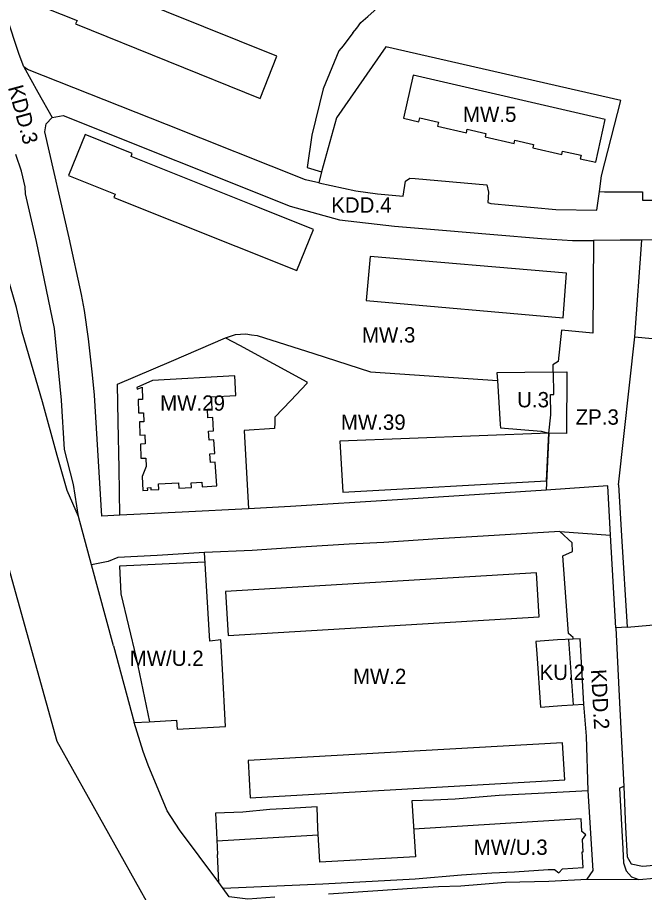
# Model space of a CAD drawing. Extents: x 7426178 to 7427732, y 5548847 to 5550287.
# Drawn here: x 7427012.7 to 7427197, y 5549022.7 to 5549279.8 of the extents above; entities that cross this region are included whole.
import ezdxf

# ---------------------------------------------------------------- set-up
doc = ezdxf.new("R2010")
doc.units = 0
for name, color, linetype in [('linie_rozgraniczajace', 7, 'Continuous'), ('linie_zabudowy_nieprzekraczalne', 7, 'Continuous'), ('linie_zabudowy_obowiazujace', 7, 'Continuous'), ('oznaczenia_przeznaczen', 7, 'Continuous')]:
    doc.layers.add(name, color=color, linetype=linetype)

msp = doc.modelspace()

# ---------------------------------------------------------------- linework, layer by layer
at = {"layer": 'linie_rozgraniczajace'}
for p, q in [((7427013.82, 5549234.68), (7427012.24, 5549239.56)), ((7427018.29, 5549214.04), (7427015, 5549228.01)), ((7427023.56, 5549188.43), (7427018.29, 5549214.04)), ((7427194.13, 5549185.96), (7427196.16, 5549214.45)), ((7427025.64, 5549167.34), (7427023.56, 5549188.43)), ((7427030.65, 5549133.22), (7427027.29, 5549140.82)), ((7427168.06, 5549140.91), (7427168.06, 5549140.91)), ((7427172.12, 5549128.78), (7427187, 5549127.76)), ((7427188.56, 5549100.49), (7427188.56, 5549100.49)), ((7427180.09, 5549026.66), (7427195.3, 5549026.51))]:
    msp.add_line(p, q, dxfattribs=at)
for points in [[(7426806.41, 5549611.72), (7426845.02, 5549569.73), (7426883.5, 5549515.53), (7426907.93, 5549461.17), (7426932.17, 5549384.03), (7426948.93, 5549331.51), (7426962.26, 5549289.73), (7427024.27, 5549067.18), (7427061.13, 5549001.37), (7427073.43, 5548973.27), (7427176.69, 5548896.63), (7427213.08, 5548849.03)], [(7427111.3, 5549275.29), (7427112.42, 5549276.71), (7427113.63, 5549278.4), (7427115.63, 5549280.17), (7427121.01, 5549284.98), (7427123.37, 5549287.21), (7427128.8, 5549292.12), (7427130.82, 5549293.83), (7427131.43, 5549294.45), (7427134.33, 5549296.6), (7427143.02, 5549303.88), (7427149.6, 5549309.36), (7427153.81, 5549312.46), (7427154.8, 5549315.39), (7427150.02, 5549327.69), (7427166.15, 5549333.81), (7427181.85, 5549339.96), (7427249.51, 5549363.69), (7427309.23, 5549379.16)], [(7427013.13, 5549268.92), (7427005.61, 5549291.59), (7427005.47, 5549294.05), (7427002.49, 5549302.88), (7427002.29, 5549306.24), (7427003.23, 5549308.53), (7427005.69, 5549310.69), (7427031.81, 5549323.48), (7427048.39, 5549331.54), (7427056.79, 5549335.77), (7427084.49, 5549349.29), (7427088.69, 5549351.18), (7427088.82, 5549351.24)], [(7427027.29, 5549140.82), (7427024.38, 5549151.16), (7427019.99, 5549166.88), (7427014.09, 5549187.33), (7427012.41, 5549194.63), (7427003.06, 5549226.37), (7426993.93, 5549257.37), (7426990.69, 5549268.36), (7426989.92, 5549277.44), (7426988.58, 5549283.13), (7426984.1, 5549295.88), (7426984.96, 5549299.25), (7426984.16, 5549301.77), (7426989.3, 5549304.41)], [(7427111.3, 5549275.29), (7427108.46, 5549271.56), (7427107.18, 5549270.01), (7427105.09, 5549265.06), (7427102.55, 5549258.9), (7427099.22, 5549245.24), (7427097.84, 5549235.74)], [(7427121, 5549271.19), (7427106.5, 5549250.33), (7427102.07, 5549234.44)], [(7427183.74, 5549228.7), (7427184.38, 5549233.33), (7427190.02, 5549255.46), (7427121, 5549271.19)], [(7427101.22, 5549231.21), (7427097.34, 5549232.16), (7427056.49, 5549248.38), (7427015.64, 5549264.59), (7427014.53, 5549265.37), (7427013.13, 5549268.92)], [(7427014.53, 5549265.37), (7427018.68, 5549257.92), (7427022.83, 5549250.47)], [(7427037.44, 5549133.27), (7427035.3, 5549168.88), (7427034.73, 5549174.79), (7427033.57, 5549185.38), (7427032.35, 5549193.71), (7427031.53, 5549198.39), (7427027.87, 5549215.06), (7427020.77, 5549246.25), (7427021.15, 5549248.57), (7427022.83, 5549250.47)], [(7427022.83, 5549250.47), (7427026.11, 5549251.01), (7427092.81, 5549224.37), (7427107.38, 5549220.37), (7427123.55, 5549218.53), (7427137.62, 5549217.31), (7427152.66, 5549216.04), (7427166.74, 5549214.87), (7427175.83, 5549214.34), (7427182.03, 5549214.34), (7427181.83, 5549187.11), (7427172.56, 5549187.95), (7427171.57, 5549178.74), (7427170.07, 5549177.78), (7427170.02, 5549175.66), (7427153.62, 5549175.37), (7427153.76, 5549173.17), (7427154.61, 5549160.21)], [(7427015, 5549228.01), (7427014.91, 5549230.12), (7427013.82, 5549234.68)], [(7427097.84, 5549235.74), (7427102.07, 5549234.44), (7427101.22, 5549231.21), (7427112.11, 5549228.91), (7427118.54, 5549228.02), (7427126.1, 5549227.31), (7427126.69, 5549231.73), (7427127.97, 5549232.67), (7427129.57, 5549232.55), (7427150.69, 5549230.7), (7427151.17, 5549228.54), (7427150.97, 5549225.49), (7427151.86, 5549225.22), (7427170.89, 5549223.46), (7427182.99, 5549223.23), (7427183.74, 5549228.7), (7427185.28, 5549228.61), (7427196.37, 5549228.64), (7427196.45, 5549226.18), (7427201.6, 5549226.15)], [(7427209.05, 5549214.51), (7427195.81, 5549214.45), (7427189.85, 5549214.39), (7427182.03, 5549214.34)], [(7427042.79, 5549133.55), (7427042.55, 5549147.3), (7427042.31, 5549161.05), (7427042.12, 5549172.05), (7427057.98, 5549178.88), (7427073.84, 5549185.71), (7427077.95, 5549183.5), (7427087.83, 5549178.16), (7427097.71, 5549172.82), (7427097.74, 5549172.25), (7427093.04, 5549167.33), (7427088.33, 5549162.42), (7427088.29, 5549160.74), (7427088.24, 5549159.06)], [(7427073.84, 5549185.71), (7427075.3, 5549186.17), (7427076.76, 5549186.64), (7427078.27, 5549186.74), (7427079.77, 5549186.83), (7427081.44, 5549186.6), (7427083.1, 5549186.37), (7427099.79, 5549181.05), (7427116.49, 5549175.74), (7427153.76, 5549173.17)], [(7427189.39, 5549142.47), (7427194.13, 5549185.96), (7427244.55, 5549181.19), (7427343.09, 5549165.77)], [(7427170.02, 5549175.66), (7427174.13, 5549175.74), (7427174.1, 5549157.56), (7427168.88, 5549157.71), (7427168.06, 5549140.91)], [(7427034.48, 5549118.98), (7427030.65, 5549133.22), (7427029.11, 5549142.56), (7427026.54, 5549152.89), (7427025.64, 5549167.34)], [(7427088.24, 5549159.06), (7427079.34, 5549158.48), (7427080.61, 5549135.5)], [(7427154.61, 5549160.21), (7427154.67, 5549159.23), (7427160.62, 5549158.75), (7427166.57, 5549158.28), (7427168.88, 5549157.71)], [(7427168.06, 5549140.91), (7427124.37, 5549138.13), (7427092.9, 5549136.14), (7427080.61, 5549135.5)], [(7427188.56, 5549100.49), (7427187, 5549127.76), (7427186.18, 5549142.24), (7427168.06, 5549140.91)], [(7427189.39, 5549142.47), (7427190.22, 5549127.54), (7427191.89, 5549100.66), (7427210.8, 5549102.38), (7427213.95, 5549102.67), (7427215.83, 5549102.92)], [(7427080.61, 5549135.5), (7427061.06, 5549134.49), (7427042.79, 5549133.55), (7427037.44, 5549133.27)], [(7427104.06, 5549022.31), (7427130.16, 5549024.09), (7427136.44, 5549024.43), (7427143.04, 5549024.69), (7427156.13, 5549025.7), (7427168.85, 5549026.02), (7427180.09, 5549026.66), (7427181.86, 5549029.14), (7427180.47, 5549052.55), (7427179.96, 5549068.69), (7427179.11, 5549078.01), (7427178.04, 5549097.27), (7427176, 5549097.13), (7427175.98, 5549097.64), (7427174.65, 5549098.78), (7427173.01, 5549121.65), (7427175.87, 5549122.87), (7427175.72, 5549125.48), (7427172.12, 5549128.78), (7427149.57, 5549127.43), (7427136.25, 5549126.63), (7427120.41, 5549125.52), (7427110.16, 5549125.1), (7427095.96, 5549124.17), (7427081.63, 5549123.25), (7427067.61, 5549122.65), (7427053.7, 5549121.78), (7427042.15, 5549121.14), (7427039.31, 5549120.02), (7427034.48, 5549118.98)], [(7427040.87, 5549095.2), (7427046.96, 5549072.63), (7427051.35, 5549072.88), (7427059.44, 5549073.34), (7427059.58, 5549070.73), (7427073.85, 5549071.46), (7427072.97, 5549088.29), (7427072.5, 5549096.98), (7427069.2, 5549096.56), (7427067.61, 5549122.65)], [(7427040.87, 5549095.2), (7427034.48, 5549118.98)], [(7427191.89, 5549100.66), (7427188.56, 5549100.49), (7427189.59, 5549080.43), (7427190.95, 5549053.83), (7427189.64, 5549053.39), (7427190.62, 5549035.51), (7427190.82, 5549031.45), (7427191.61, 5549029.08), (7427193.18, 5549027.34), (7427195.3, 5549026.51), (7427204.57, 5549027.34), (7427204.74, 5549027.89), (7427217.64, 5549028.9), (7427230.78, 5549029.62), (7427244.12, 5549030.67)], [(7427176, 5549097.13), (7427171.41, 5549096.93), (7427165.09, 5549096.51), (7427165.31, 5549092.8), (7427166.42, 5549077.16), (7427172.69, 5549077.63), (7427179.11, 5549078.01)], [(7427088.36, 5549021.31), (7427080.37, 5549020.78), (7427074.88, 5549021.46), (7427071.9, 5549025.67), (7427060.27, 5549041.15), (7427056.72, 5549046.74), (7427051.09, 5549060.09), (7427049.64, 5549064.12), (7427046.96, 5549072.63)], [(7427180.47, 5549052.55), (7427167.58, 5549051.89), (7427154.23, 5549051.2), (7427141.38, 5549050.18), (7427134.93, 5549049.84), (7427128.64, 5549049.66)], [(7427128.64, 5549049.66), (7427129.64, 5549033.23), (7427101.59, 5549031.65), (7427100.99, 5549041.51), (7427100.81, 5549047.84), (7427092.56, 5549047.43), (7427086.89, 5549047.09), (7427078.95, 5549046.33), (7427070.87, 5549046.05), (7427071.17, 5549040.31), (7427071.49, 5549033.9)], [(7427071.9, 5549025.67), (7427071.49, 5549033.9)]]:
    msp.add_lwpolyline(points, dxfattribs=at)
at = {"layer": 'linie_zabudowy_nieprzekraczalne'}
msp.add_line((7427176.08, 5549077.83), (7427174.77, 5549097.08), dxfattribs=at)
for points in [[(7427168.88, 5549157.71), (7427169.46, 5549163.09), (7427169.35, 5549169.04), (7427170.38, 5549169.05), (7427170.26, 5549175.67)], [(7427067.79, 5549119.74), (7427042.67, 5549118.59), (7427043.04, 5549110.48), (7427047.53, 5549091.64), (7427051.52, 5549072.89)], [(7427188.56, 5549100.49), (7427189.59, 5549080.43), (7427190.95, 5549053.83), (7427191.36, 5549041.76), (7427191.91, 5549033.22), (7427193.09, 5549031.1)], [(7427178.37, 5549044.36), (7427129.15, 5549041.33)], [(7427101.1, 5549039.6), (7427071.3, 5549037.76)]]:
    msp.add_lwpolyline(points, dxfattribs=at)
msp.add_lwpolyline([(7427168.88, 5549157.71), (7427107.45, 5549155.3), (7427108.29, 5549140.35), (7427168.2, 5549143.7)], close=True, dxfattribs=at)
at = {"layer": 'linie_zabudowy_obowiazujace'}
for points in [[(7427088.96, 5549268.43), (7427035.01, 5549290.19), (7427035.3, 5549290.91), (7427021.52, 5549296.47), (7427016.64, 5549284.38), (7427030.18, 5549278.92), (7427029.78, 5549277.94), (7427083.97, 5549256.08), (7427088.96, 5549268.43)], [(7427185.47, 5549249.83), (7427128.95, 5549262.91), (7427126.18, 5549250.21), (7427130.66, 5549249.18), (7427130.92, 5549250.32), (7427136.45, 5549249.05), (7427136.19, 5549247.92), (7427144.67, 5549245.98), (7427144.9, 5549246.99), (7427150.37, 5549245.73), (7427150.14, 5549244.73), (7427158.66, 5549242.78), (7427158.89, 5549243.79), (7427164.36, 5549242.53), (7427164.13, 5549241.53), (7427172.66, 5549239.58), (7427172.89, 5549240.58), (7427178.35, 5549239.35), (7427178.12, 5549238.33), (7427182.7, 5549237.28), (7427185.47, 5549249.83)], [(7427083.33, 5549224.07), (7427046.06, 5549238.96), (7427046.44, 5549239.86), (7427032.57, 5549245.47), (7427027.69, 5549233.43), (7427041.35, 5549227.93), (7427040.99, 5549226.99), (7427094.83, 5549205.45), (7427099.73, 5549217.52), (7427083.33, 5549224.07)], [(7427116.32, 5549209.65), (7427115.18, 5549196.64), (7427173.05, 5549191.6), (7427174.11, 5549204.68), (7427116.32, 5549209.65)], [(7427047.81, 5549171.15), (7427047.83, 5549170.6), (7427049.31, 5549171.21), (7427049.43, 5549167.6), (7427048.12, 5549167.55), (7427048.25, 5549163.63), (7427049.73, 5549163.68), (7427049.82, 5549161.06), (7427048.52, 5549161.01), (7427048.65, 5549157.14), (7427050.12, 5549157.19), (7427050.21, 5549154.51), (7427048.83, 5549154.46), (7427048.97, 5549150.31), (7427050.38, 5549150.37), (7427050.48, 5549147.93), (7427049.31, 5549144.92), (7427049.56, 5549140.87), (7427050.99, 5549140.96), (7427050.95, 5549141.65), (7427051.89, 5549141.71), (7427051.93, 5549141.02), (7427054.28, 5549141.16), (7427054.18, 5549142.77), (7427060.03, 5549143.12), (7427060.13, 5549141.49), (7427063.85, 5549141.71), (7427063.77, 5549143.1), (7427066.84, 5549143.28), (7427066.93, 5549141.91), (7427071.24, 5549142.17), (7427070.82, 5549149.17), (7427069.41, 5549149.08), (7427069.25, 5549151.65), (7427070.67, 5549151.74), (7427070.43, 5549155.72), (7427069.03, 5549155.63), (7427068.88, 5549158.26), (7427070.29, 5549158.35), (7427070.06, 5549162.25), (7427068.65, 5549162.16), (7427068.49, 5549164.75), (7427069.9, 5549164.83), (7427069.69, 5549168.36), (7427076.9, 5549168.71), (7427076.56, 5549174.55), (7427052.41, 5549173.16), (7427047.81, 5549171.15)], [(7427073.85, 5549111.14), (7427074.64, 5549098.23), (7427166.02, 5549103.76), (7427165.24, 5549116.68), (7427073.85, 5549111.14)], [(7427080.46, 5549061.45), (7427081.08, 5549050.52), (7427173.53, 5549055.77), (7427172.91, 5549066.71), (7427080.46, 5549061.45)], [(7427073.12, 5549023.95), (7427102.46, 5549025.22), (7427129.58, 5549026.74), (7427143.19, 5549027.88), (7427152.16, 5549028.49), (7427158.8, 5549028.78), (7427168.68, 5549029.46), (7427170.58, 5549029.5), (7427171.81, 5549028.5), (7427172.88, 5549029.65), (7427178.94, 5549030.07), (7427178.66, 5549034.66), (7427178.93, 5549034.68), (7427178.75, 5549038.28), (7427179.77, 5549039.66), (7427178.6, 5549040.62), (7427178.37, 5549044.36)], [(7427193.09, 5549031.1), (7427196.43, 5549030.48), (7427204.46, 5549031.16), (7427212.47, 5549031.85), (7427230.95, 5549033.41), (7427243.99, 5549033.59)]]:
    msp.add_lwpolyline(points, dxfattribs=at)

# ---------------------------------------------------------------- texts
at = {"layer": 'oznaczenia_przeznaczen'}
for s, rotation, p in [('KDD.3', 285.3489, (7427009.85, 5549259.28)), ('KDD.2', 273.1717, (7427181.24, 5549088.21))]:
    msp.add_text(s, height=4.5, rotation=rotation, dxfattribs=at).set_placement(p)
for s, p in [('MW.5', (7427143.63, 5549249.16)), ('KDD.4', (7427104.9, 5549222.49)), ('MW.3', (7427113.93, 5549184.33)), ('U.3', (7427159.56, 5549165.28)), ('MW.29', (7427054.62, 5549164.29)), ('ZP.3', (7427176.74, 5549160.18)), ('MW.39', (7427107.73, 5549158.67)), ('MW/U.2', (7427045.67, 5549089.3)), ('KU.2', (7427166.14, 5549085.16)), ('MW.2', (7427111.28, 5549083.97)), ('MW/U.3', (7427146.79, 5549033.77))]:
    msp.add_text(s, height=4.5, dxfattribs=at).set_placement(p)

doc.saveas('drawing.dxf')
